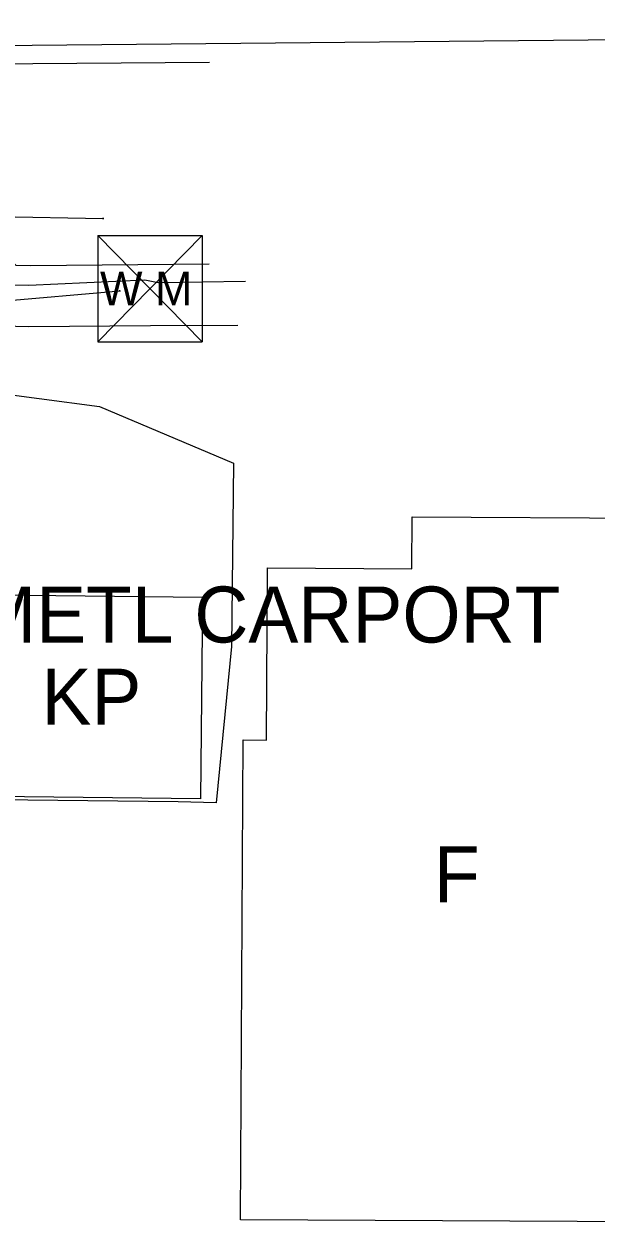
# Model space of a CAD drawing. Extents: x 1304270 to 1306561, y 1876019 to 1876752.
# Drawn here: x 1306338 to 1306389.1, y 1876311.8 to 1876418.8 of the extents above; entities that cross this region are included whole.
import ezdxf

# ---------------------------------------------------------------- set-up
doc = ezdxf.new("R2010")
doc.units = 0
for name, color, linetype in [('S_BUILDING', 7, 'Continuous'), ('S_BUILDING_ANNOT', 7, 'Continuous'), ('S_DRIVEWAY', 7, 'Continuous'), ('S_EDGE_PAVEMENT', 7, 'Continuous'), ('S_FIBER_OPTIC_CABLE', 7, 'Continuous'), ('S_GAS_UTILITIES', 7, 'Continuous'), ('S_PAVEMENT_CROWN', 7, 'Continuous'), ('S_SANITARY_SEWER', 7, 'Continuous'), ('S_SIDEWALK', 7, 'Continuous'), ('S_SURVEY_TEXT_ANNOT', 7, 'Continuous'), ('S_UTL_PT_SYM', 7, 'Continuous'), ('S_WATER_UTILITIES', 7, 'Continuous')]:
    doc.layers.add(name, color=color, linetype=linetype)

msp = doc.modelspace()

# ---------------------------------------------------------------- linework, layer by layer
at = {"layer": 'S_BUILDING'}
for points in [[(1306393.78, 1876374.66), (1306393.43, 1876311.79), (1306357.34, 1876311.99), (1306357.57, 1876354.84), (1306359.66, 1876354.83), (1306359.74, 1876370.2), (1306372.64, 1876370.13), (1306372.67, 1876374.78)], [(1306332.98, 1876367.83), (1306353.96, 1876367.59), (1306353.76, 1876349.58), (1306332.78, 1876349.82)]]:
    msp.add_lwpolyline(points, close=True, dxfattribs=at)
at = {"layer": 'S_DRIVEWAY'}
msp.add_lwpolyline([(1306323.18, 1876387.47), (1306344.74, 1876384.62), (1306356.72, 1876379.57), (1306356.54, 1876363.18), (1306355.17, 1876349.22), (1306351.78, 1876349.32), (1306332.95, 1876349.51), (1306318.29, 1876350.28)], dxfattribs=at)
at = {"layer": 'S_EDGE_PAVEMENT'}
msp.add_lwpolyline([(1306165.48, 1876396.19), (1306188.31, 1876396.43), (1306201.55, 1876396.99), (1306203.51, 1876397.54), (1306207.41, 1876397.36), (1306207.63, 1876397.16), (1306215.41, 1876396.62), (1306234.61, 1876396.75), (1306255.38, 1876396.73), (1306279.47, 1876397.14), (1306280.07, 1876397.39), (1306281.48, 1876397.3), (1306281.94, 1876397.15), (1306288.47, 1876397.22), (1306311.84, 1876397.17), (1306330.84, 1876397.38), (1306332.77, 1876398.02), (1306334.38, 1876398.14), (1306335.31, 1876398.67), (1306336.28, 1876398.38), (1306337.28, 1876397.24), (1306338.63, 1876397.21), (1306354.54, 1876397.37)], dxfattribs=at)
at = {"layer": 'S_FIBER_OPTIC_CABLE'}
msp.add_line((1306327.13, 1876401.75), (1306345.07, 1876401.41), dxfattribs=at)
at = {"layer": 'S_GAS_UTILITIES'}
msp.add_line((1306334.96, 1876393.93), (1306346.57, 1876394.94), dxfattribs=at)
at = {"layer": 'S_PAVEMENT_CROWN'}
msp.add_lwpolyline([(1306053.64, 1876411.74), (1306078.45, 1876411.98), (1306096.34, 1876412.19), (1306114.22, 1876412.39), (1306129.3, 1876412.61), (1306144.38, 1876412.83), (1306159.45, 1876413.06), (1306174.53, 1876413.28), (1306194.7, 1876413.58), (1306214.87, 1876413.88), (1306234.9, 1876413.74), (1306250.98, 1876414.03), (1306267.06, 1876414.33), (1306289.97, 1876414.14), (1306302.49, 1876414.59), (1306315, 1876415.05), (1306334.8, 1876415.21), (1306354.59, 1876415.38)], dxfattribs=at)
at = {"layer": 'S_SANITARY_SEWER'}
msp.add_line((1306535.55, 1876418.78), (1306311.23, 1876416.59), dxfattribs=at)
at = {"layer": 'S_SIDEWALK'}
for points in [[(1306332.6, 1876395.5), (1306338.44, 1876395.45), (1306348.81, 1876395.93), (1306349.98, 1876395.68), (1306357.8, 1876395.81)], [(1306330.28, 1876391.97), (1306338.44, 1876391.76), (1306349.3, 1876391.86), (1306357.11, 1876391.89)]]:
    msp.add_lwpolyline(points, dxfattribs=at)
at = {"layer": 'S_UTL_PT_SYM'}
for points in [[(1306345.07, 1876401.41), (1306345.07, 1876401.46), (1306345.07, 1876401.41), (1306345.02, 1876401.41), (1306345.07, 1876401.41), (1306345.07, 1876401.36), (1306345.07, 1876401.41), (1306345.12, 1876401.41)], [(1306346.57, 1876394.94), (1306346.57, 1876394.99), (1306346.57, 1876394.94), (1306346.52, 1876394.94), (1306346.57, 1876394.94), (1306346.57, 1876394.89), (1306346.57, 1876394.94), (1306346.62, 1876394.94)]]:
    msp.add_lwpolyline(points, dxfattribs=at)
at = {"layer": 'S_WATER_UTILITIES'}
for p, q in [((1306344.59, 1876399.89), (1306353.93, 1876399.89)), ((1306344.59, 1876399.89), (1306344.59, 1876390.39)), ((1306344.59, 1876399.89), (1306353.93, 1876390.39)), ((1306353.93, 1876399.89), (1306344.59, 1876390.39)), ((1306353.93, 1876399.89), (1306353.93, 1876390.39)), ((1306344.59, 1876390.39), (1306353.93, 1876390.39))]:
    msp.add_line(p, q, dxfattribs=at)

# ---------------------------------------------------------------- texts
at = {"layer": 'S_BUILDING_ANNOT'}
for s, p in [('KP', (1306339.57, 1876356.2)), ('F', (1306374.62, 1876340.33))]:
    msp.add_text(s, height=5, dxfattribs=at).set_placement(p)
at = {"layer": 'S_SURVEY_TEXT_ANNOT'}
msp.add_text('METL CARPORT', height=5, dxfattribs=at).set_placement((1306333.53, 1876363.54))
at = {"layer": 'S_WATER_UTILITIES'}
msp.add_text('W M', height=3, rotation=360, dxfattribs=at).set_placement((1306344.8, 1876393.65))

doc.saveas('drawing.dxf')
